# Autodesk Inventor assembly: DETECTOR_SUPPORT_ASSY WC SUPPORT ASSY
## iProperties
Shininess: 64.0
Length Units: 11272
Angle Units: 11279
Time Units: 11290
Mass Units: 11286
Length Display Precision: 3
Angle Display Precision: 2
Compacted: True
Part Number: DETECTOR_SUPPORT_ASSY WC SUPPORT ASSY
Document SubType Name: Assembly
Created: 2004-08
Designer: John Blackburn
Manufacturer: Standard
Standards Organization: Custom
Density: 0.0
Volumn: 0.0
Area: 0.0
PropertySet Name: Model Information
Control State: 0
Master: False
Checked Out: False
Author: John Blackburn
